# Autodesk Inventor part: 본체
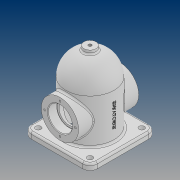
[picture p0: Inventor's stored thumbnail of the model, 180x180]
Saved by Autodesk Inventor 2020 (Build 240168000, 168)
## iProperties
Created: 2021-08
Part Number: 본체
Material: 일반
Document SubType Name: Modeling
Designer: PC312-
Density: 1 g/cm^3
Appearance: 기본값
Author: PC312-
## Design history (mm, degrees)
sketch "스케치1"
  geometry: C1 r 40 at (0, 0); 1 further point
  constraints: 1 centre point, 1 coincident
  dimensions: "d0" = 80 diameter of C1
extrude "돌출1" new body sketch "스케치1" distance "d1" = 84; taper "d2" = 0 deg
sketch "스케치3"
  geometry: C1 r 40 at (0, 0) reference; 1 further point
extrude "돌출3" join sketch "스케치3" distance "d7" = 40; taper "d8" = 0 deg
fillet "모깎기1" dims "d9" = 40
feature "쉘1" dims "d10" = 8
sketch "스케치2"
  geometry: L1 (-55, 55)-(55, 55); L2 (55, 55)-(55, -55); L3 (55, -55)-(-55, -55); L4 (-55, -55)-(-55, 55); L5 (-55, 55)-(55, -55); L6 (55, 55)-(-55, -55); 1 further point
  constraints: 12 end point, 2 midpoint, 2 parallel, 1 horizontal, 1 perpendicular
  dimensions: "d3" = 110 distance of L2.end L3.end; "d4" = 110 distance of L1.end L2.end
extrude "돌출2" join sketch "스케치2" distance "d5" = 10; taper "d6" = 0 deg
sketch "스케치5"
  geometry: C1 r 31 at (0, 48); 1 further point
  constraints: 1 centre point, 1 vertical alignment
  dimensions: "d13" = 62 diameter of C1; "d14" = 48 distance of point (0, 0) C1.centre
extrude "돌출5" join sketch "스케치5" stored distance "d15" = 100; taper "d16" = 0 deg
sketch "스케치6"
  geometry: C1 r 20 at (0, 0); C2 r 31 at (0, 0) reference; 1 further point
  constraints: 1 centre point, 1 concentric
  dimensions: "d17" = 40 diameter of C1
extrude "돌출6" cut sketch "스케치6" distance "d18" = 15; taper "d19" = 0 deg
sketch "스케치7"
  geometry: C1 r 20 at (0, 0) reference; A1 r 25.5 centre (0, 0) between (0, 25.5) and (0, -25.5); 3 further points
  constraints: 4 point on circle, 2 horizontal alignment, 2 vertical alignment, 1 centre point, 1 concentric
  dimensions: "d20" = 51 diameter of A1
hole "구멍1" sketch "스케치7" at (0, 25.5), (0, -25.5), (25.5, 0), (-25.5, 0) diameter "d21" = 3.242; stored, may be unused: countersink angle "d25" = 90 deg, drill point angle "d27" = 118 deg; dims "d22" = 8, "d23" = 4, "d24" = 2, "d26" = 10
sketch "스케치8"
  geometry: C1 r 16.5 at (0, 0); C2 r 20 at (0, 0) reference; 1 further point
  constraints: 1 centre point, 1 concentric
  dimensions: "d28" = 33 diameter of C1
extrude "돌출7" cut sketch "스케치8" extent not by distance; stored distance "d29" = 15; taper "d30" = 0 deg
sketch "스케치4"
  geometry: C1 r 32 at (0, 0) reference; 1 further point
extrude "돌출4" cut sketch "스케치4" stored distance "d11" = 144; taper "d12" = 0 deg
node "작업 평면1"
sketch "스케치9"
  geometry: C1 r 10 at (0, 0); 1 further point
  constraints: 1 centre point, 1 coincident
  dimensions: "d32" = 20 diameter of C1
extrude "돌출8" join sketch "스케치9" stored distance "d33" = 10; taper "d34" = 0 deg
sketch "스케치10"
  geometry: 2 further points
  constraints: 1 coincident
hole "구멍2" sketch "스케치10" at (0, 0) diameter "d35" = 5.1881; stored, may be unused: countersink angle "d39" = 90 deg, drill point angle "d41" = 0 deg; dims "d36" = 12, "d37" = 4, "d38" = 2, "d40" = 16
fillet "모깎기2" dims "d42" = 0.3
chamfer "모따기1" distance "d43" = 1; stored, may be unused: second distance "d44" = 2, angle "d45" = 45 deg
node "작업 평면2"
sketch "스케치11"
  geometry: L1 (0, -55)-(0, 55) reference; 3 further points
  constraints: 1 horizontal alignment, 1 midpoint, 1 other
  dimensions: "d47" = 48 distance from line of L1 point (48, 0)
feature "엠보싱1" sketch "스케치11" dims "d48" = 0.5, "d49" = 0
fillet "모깎기3" dims "d50" = 12
sketch "스케치12"
  geometry: C1 r 4.5 at (-43, 43); A1 r 12 centre (-43, 43) between (-43, 55) and (-55, 43) reference; 1 further point
  constraints: 1 centre point, 1 concentric
  dimensions: "d51" = 9 diameter of C1
extrude "돌출9" cut sketch "스케치12" extent not by distance; stored distance "d52" = 0; taper "d53" = 0 deg
fillet "모깎기4" dims "d57" = 3
node "솔리드1"
mirror "미러1"
pattern_circular "원형 패턴1" dims angle "d55" = 360 deg
feature "A9D066F2-1C7D-4E18-AEED-F7BC21143FA4" dims "d21" = 3.242, "d22" = 8, "d23" = 4, "d24" = 2, "d25" = 90 deg, "d26" = 10, "d27" = 118 deg
other parameters: "d31" = -129, "d46" = 83.75
